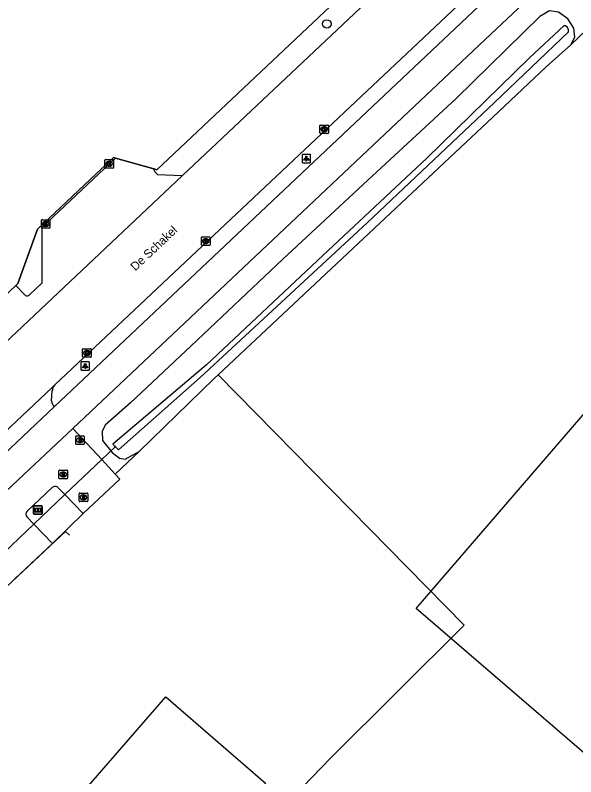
# Model space of a CAD drawing. Extents: x 156141 to 158132, y 385651 to 388399.
# Drawn here: x 156374.9 to 156440.2, y 387384.8 to 387473.5 of the extents above; entities that cross this region are included whole.
import ezdxf

# ---------------------------------------------------------------- set-up
doc = ezdxf.new("R2010")
doc.units = 0
for name, color, linetype in [('IMGEO_Berm_groen', 7, 'Continuous'), ('IMGEO_Boom', 7, 'Continuous'), ('IMGEO_Brandkraan', 7, 'Continuous'), ('IMGEO_Duiker', 7, 'Continuous'), ('IMGEO_Erf', 7, 'Continuous'), ('IMGEO_Fietspad_gesloten', 7, 'Continuous'), ('IMGEO_Grasland_agrarisch', 7, 'Continuous'), ('IMGEO_Groenvoorziening', 7, 'Continuous'), ('IMGEO_Hek', 7, 'Continuous'), ('IMGEO_Informatiebord', 7, 'Continuous'), ('IMGEO_Kolk', 7, 'Continuous'), ('IMGEO_Lichtpunt', 7, 'Continuous'), ('IMGEO_Openbare_ruimte_label', 7, 'Continuous'), ('IMGEO_Pand', 7, 'Continuous'), ('IMGEO_Pand_vergunning_verleend', 7, 'Continuous'), ('IMGEO_Rijbaan_lokaal_gesloten', 7, 'Continuous'), ('IMGEO_Rijbaan_lokaal_open', 7, 'Continuous'), ('IMGEO_Rioolput', 7, 'Continuous'), ('IMGEO_Waterloop', 7, 'Continuous')]:
    doc.layers.add(name, color=color, linetype=linetype)

msp = doc.modelspace()

# ---------------------------------------------------------------- linework, layer by layer
at = {"layer": 'IMGEO_Berm_groen'}
for points in [[(156391.052, 387455.634), (156391.387, 387455.539), (156425.089, 387487.348), (156452.106, 387512.72), (156457.451, 387517.769)], [(156439.579, 387470.075), (156445.188, 387475.47)], [(156439.579, 387470.075), (156440.055, 387470.978), (156439.936, 387472.035), (156439.259, 387473.121), (156438.152, 387473.891), (156437.128, 387474.069), (156435.984, 387473.375), (156426.238, 387463.827), (156415.973, 387454.322), (156406.042, 387445.13), (156395.379, 387435.028), (156388.319, 387428.383), (156385.37, 387425.775), (156385.007, 387425.036), (156385.052, 387424.008), (156386.187, 387422.587), (156387.045, 387421.935), (156387.718, 387421.807), (156389.316, 387422.698)], [(156386.547, 387420.081), (156389.316, 387422.698)], [(156382.82, 387415.469), (156379.24, 387412.002)]]:
    msp.add_lwpolyline(points, dxfattribs=at)
at = {"layer": 'IMGEO_Boom'}
msp.add_circle((156411.182, 387472.533), 0.489, dxfattribs=at)
at = {"layer": 'IMGEO_Brandkraan'}
for p, q in [((156381.941, 387423.601), (156381.941, 387424.453)), ((156382.016, 387424.527), (156382.868, 387424.527)), ((156382.429, 387424.307), (156382.454, 387424.307)), ((156382.942, 387424.453), (156382.942, 387423.601)), ((156382.868, 387423.527), (156382.016, 387423.527)), ((156382.452, 387423.747), (156382.427, 387423.747))]:
    msp.add_line(p, q, dxfattribs=at)
for points in [[(156381.941, 387423.601), (156381.941, 387424.453)], [(156382.016, 387424.527), (156382.868, 387424.527)], [(156382.289, 387424.227), (156382.289, 387423.827), (156382.502, 387423.827)], [(156382.52, 387424.227), (156382.289, 387424.227)], [(156382.942, 387424.453), (156382.942, 387423.601)], [(156382.868, 387423.527), (156382.016, 387423.527)], [(156382.468, 387424.146), (156382.414, 387424.146), (156382.414, 387424.07)], [(156382.414, 387424.07), (156382.467, 387424.07)], [(156382.476, 387423.994), (156382.414, 387423.994), (156382.414, 387423.913)], [(156382.414, 387423.913), (156382.476, 387423.913)]]:
    msp.add_lwpolyline(points, dxfattribs=at)
for centre, radius, start, end in [((156382.018, 387424.451), 0.0765, 91.55205, 178.44795), ((156382.018, 387424.451), 0.0765, 91.55205, 178.44795), ((156382.524, 387424.082), 0.145, 59.4692, 91.53667), ((156382.866, 387424.451), 0.0765, 1.55205, 88.44795), ((156382.866, 387424.451), 0.0765, 1.55205, 88.44795), ((156382.018, 387423.603), 0.0765, 181.55205, 268.44795), ((156382.018, 387423.603), 0.0765, 181.55205, 268.44795), ((156382.469, 387424.108), 0.0379, 267.82845, 90.93552), ((156382.477, 387423.953), 0.0404, 269.87594, 90.50774), ((156382.508, 387424.078), 0.251, 268.66757, 293.53466), ((156382.549, 387424.129), 0.0922, 285.51372, 58.15012), ((156382.554, 387423.937), 0.105, 301.31148, 78.98903), ((156382.866, 387423.603), 0.0765, 271.55205, 358.44795), ((156382.866, 387423.603), 0.0765, 271.55205, 358.44795)]:
    msp.add_arc(centre, radius, start, end, dxfattribs=at)
for centre, major_axis, ratio, start_param, end_param in [((156382.428, 387424.027), (-0.387, 0.002), 0.722429, 4.712389, 7.853982), ((156382.453, 387424.027), (-0.39, 0.002), 0.717154, 1.570796, 4.712389)]:
    msp.add_ellipse(centre, major_axis=major_axis, ratio=ratio, start_param=start_param, end_param=end_param, dxfattribs=at)
at = {"layer": 'IMGEO_Duiker'}
msp.add_lwpolyline([(156370.963, 387408.483), (156372.047, 387409.51), (156372.712, 387410.141), (156377.057, 387414.261), (156380.682, 387417.698), (156384.979, 387421.773), (156385.729, 387422.483), (156386.614, 387423.323)], dxfattribs=at)
at = {"layer": 'IMGEO_Erf'}
msp.add_lwpolyline([(156389.316, 387422.698), (156398.063, 387431.195), (156398.534, 387431.637)], dxfattribs=at)
at = {"layer": 'IMGEO_Fietspad_gesloten'}
for points in [[(156585.415, 387620.086), (156578.126, 387613.433), (156551.398, 387590.304), (156495.527, 387537.568), (156379.452, 387427.902)], [(156590.669, 387620.135), (156581.442, 387611.597), (156554.376, 387588.321), (156498.217, 387535.194), (156430.268, 387471.316), (156381.614, 387425.402)]]:
    msp.add_lwpolyline(points, dxfattribs=at)
at = {"layer": 'IMGEO_Grasland_agrarisch'}
for points in [[(156398.534, 387431.637), (156430.521, 387461.648), (156436.708, 387467.537), (156439.579, 387470.075)], [(156406.207, 387381.373), (156411.668, 387387.025), (156427.155, 387402.46), (156398.534, 387431.637)]]:
    msp.add_lwpolyline(points, dxfattribs=at)
at = {"layer": 'IMGEO_Groenvoorziening'}
msp.add_lwpolyline([(156374.956, 387442.047), (156375.204, 387442.28), (156377.511, 387448.6), (156386.35, 387456.964), (156386.592, 387456.896)], dxfattribs=at)
at = {"layer": 'IMGEO_Hek'}
for points in [[(156548.867, 387605.742), (156540.59, 387597.212), (156536.23, 387592.718), (156529.863, 387586.065), (156510.629, 387567.966), (156497.455, 387555.488), (156496.881, 387556.093), (156495.089, 387554.361), (156495.654, 387553.795), (156471.142, 387530.701), (156467.766, 387527.512), (156457.451, 387517.769), (156452.106, 387512.72), (156425.089, 387487.348), (156391.387, 387455.539), (156391.052, 387455.634), (156386.592, 387456.896), (156386.35, 387456.964), (156377.511, 387448.6), (156375.204, 387442.28), (156374.956, 387442.047), (156370.988, 387438.316), (156367.952, 387435.462), (156364.053, 387431.796)], [(156343.435, 387366.714), (156343.833, 387368.977), (156344.263, 387371.266), (156344.924, 387373.465), (156345.713, 387375.673), (156346.624, 387377.803), (156347.657, 387379.878), (156348.858, 387381.869), (156350.164, 387383.782), (156351.592, 387385.597), (156353.137, 387387.325), (156354.792, 387388.966), (156373.938, 387406.992), (156380.213, 387412.891), (156380.728, 387413.365)], [(156381.228, 387412.955), (156380.732, 387413.408)]]:
    msp.add_lwpolyline(points, dxfattribs=at)
at = {"layer": 'IMGEO_Informatiebord'}
for p, q in [((156377.039, 387415.491), (156377.039, 387416.291)), ((156377.039, 387416.291), (156377.039, 387415.491)), ((156377.139, 387416.391), (156377.929, 387416.391)), ((156377.929, 387416.391), (156377.139, 387416.391)), ((156378.029, 387416.291), (156378.029, 387415.491)), ((156378.029, 387415.491), (156378.029, 387416.291)), ((156377.929, 387415.391), (156377.139, 387415.391)), ((156377.139, 387415.391), (156377.929, 387415.391))]:
    msp.add_line(p, q, dxfattribs=at)
for points in [[(156377.14, 387416.123), (156377.928, 387416.123), (156377.928, 387415.659), (156377.14, 387415.659), (156377.14, 387416.123)], [(156377.205, 387416.058), (156377.205, 387415.724), (156377.48, 387415.724), (156377.481, 387415.937), (156377.585, 387415.938), (156377.586, 387415.724), (156377.863, 387415.724), (156377.863, 387416.058), (156377.587, 387416.058), (156377.587, 387415.978), (156377.481, 387415.978), (156377.481, 387416.058), (156377.205, 387416.058)]]:
    msp.add_lwpolyline(points, dxfattribs=at)
for centre, start, end in [((156377.139, 387416.291), 90, 180), ((156377.139, 387416.291), 90, 180), ((156377.929, 387416.291), 0, 90), ((156377.929, 387416.291), 360, 90), ((156377.139, 387415.491), 180, 270), ((156377.139, 387415.491), 180, 270), ((156377.929, 387415.491), 270, 0), ((156377.929, 387415.491), 270, 0)]:
    msp.add_arc(centre, 0.1, start, end, dxfattribs=at)
at = {"layer": 'IMGEO_Kolk'}
for p, q in [((156410.371, 387459.823), (156410.371, 387460.675)), ((156410.446, 387460.749), (156411.298, 387460.749)), ((156411.372, 387460.675), (156411.372, 387459.823)), ((156411.298, 387459.749), (156410.446, 387459.749)), ((156410.882, 387459.969), (156410.857, 387459.969)), ((156410.859, 387460.529), (156410.884, 387460.529)), ((156385.33, 387455.789), (156385.33, 387456.641)), ((156385.405, 387456.715), (156386.257, 387456.715)), ((156385.818, 387456.495), (156385.843, 387456.495)), ((156386.331, 387456.641), (156386.331, 387455.789)), ((156386.257, 387455.715), (156385.405, 387455.715)), ((156385.841, 387455.935), (156385.816, 387455.935)), ((156377.946, 387448.794), (156377.946, 387449.646)), ((156378.021, 387449.72), (156378.873, 387449.72)), ((156378.434, 387449.5), (156378.459, 387449.5)), ((156378.947, 387449.646), (156378.947, 387448.794)), ((156378.873, 387448.72), (156378.021, 387448.72)), ((156378.457, 387448.94), (156378.432, 387448.94)), ((156396.581, 387446.796), (156396.581, 387447.648)), ((156396.656, 387447.722), (156397.508, 387447.722)), ((156397.069, 387447.502), (156397.094, 387447.502)), ((156397.582, 387447.648), (156397.582, 387446.796)), ((156397.508, 387446.722), (156396.656, 387446.722)), ((156397.092, 387446.942), (156397.067, 387446.942)), ((156382.748, 387433.761), (156382.748, 387434.613)), ((156382.823, 387434.687), (156383.675, 387434.687)), ((156383.236, 387434.467), (156383.261, 387434.467)), ((156383.749, 387434.613), (156383.749, 387433.761)), ((156383.675, 387433.687), (156382.823, 387433.687)), ((156383.259, 387433.907), (156383.234, 387433.907))]:
    msp.add_line(p, q, dxfattribs=at)
for points in [[(156410.371, 387459.823), (156410.371, 387460.675)], [(156410.446, 387460.749), (156411.298, 387460.749)], [(156411.372, 387460.675), (156411.372, 387459.823)], [(156411.298, 387459.749), (156410.446, 387459.749)], [(156410.692, 387460.449), (156410.815, 387460.449), (156410.815, 387460.298), (156410.945, 387460.449), (156411.109, 387460.449), (156410.963, 387460.298), (156411.116, 387460.049), (156410.964, 387460.049), (156410.879, 387460.213), (156410.815, 387460.146), (156410.815, 387460.049), (156410.692, 387460.049), (156410.692, 387460.449)], [(156385.33, 387455.789), (156385.33, 387456.641)], [(156385.405, 387456.715), (156386.257, 387456.715)], [(156385.651, 387456.415), (156385.774, 387456.415), (156385.774, 387456.264), (156385.904, 387456.415), (156386.068, 387456.415), (156385.922, 387456.264), (156386.075, 387456.015), (156385.923, 387456.015), (156385.838, 387456.179), (156385.774, 387456.112), (156385.774, 387456.015), (156385.651, 387456.015), (156385.651, 387456.415)], [(156386.331, 387456.641), (156386.331, 387455.789)], [(156386.257, 387455.715), (156385.405, 387455.715)], [(156377.946, 387448.794), (156377.946, 387449.646)], [(156378.021, 387449.72), (156378.873, 387449.72)], [(156378.267, 387449.42), (156378.39, 387449.42), (156378.39, 387449.269), (156378.52, 387449.42), (156378.684, 387449.42), (156378.538, 387449.269), (156378.691, 387449.02), (156378.539, 387449.02), (156378.454, 387449.184), (156378.39, 387449.117), (156378.39, 387449.02), (156378.267, 387449.02), (156378.267, 387449.42)], [(156378.947, 387449.646), (156378.947, 387448.794)], [(156378.873, 387448.72), (156378.021, 387448.72)], [(156396.581, 387446.796), (156396.581, 387447.648)], [(156396.656, 387447.722), (156397.508, 387447.722)], [(156396.902, 387447.422), (156397.025, 387447.422), (156397.025, 387447.271), (156397.155, 387447.422), (156397.319, 387447.422), (156397.173, 387447.271), (156397.326, 387447.022), (156397.174, 387447.022), (156397.089, 387447.186), (156397.025, 387447.119), (156397.025, 387447.022), (156396.902, 387447.022), (156396.902, 387447.422)], [(156397.582, 387447.648), (156397.582, 387446.796)], [(156397.508, 387446.722), (156396.656, 387446.722)], [(156382.748, 387433.761), (156382.748, 387434.613)], [(156382.823, 387434.687), (156383.675, 387434.687)], [(156383.069, 387434.387), (156383.192, 387434.387), (156383.192, 387434.236), (156383.322, 387434.387), (156383.486, 387434.387), (156383.34, 387434.236), (156383.493, 387433.987), (156383.341, 387433.987), (156383.256, 387434.151), (156383.192, 387434.084), (156383.192, 387433.987), (156383.069, 387433.987), (156383.069, 387434.387)], [(156383.749, 387434.613), (156383.749, 387433.761)], [(156383.675, 387433.687), (156382.823, 387433.687)]]:
    msp.add_lwpolyline(points, dxfattribs=at)
for centre, start, end in [((156410.448, 387460.673), 91.55205, 178.44795), ((156410.448, 387460.673), 91.55205, 178.44795), ((156411.296, 387460.673), 1.55205, 88.44795), ((156411.296, 387460.673), 1.55205, 88.44795), ((156410.448, 387459.825), 181.55205, 268.44795), ((156410.448, 387459.825), 181.55205, 268.44795), ((156411.296, 387459.825), 271.55205, 358.44795), ((156411.296, 387459.825), 271.55205, 358.44795), ((156385.407, 387456.639), 91.55205, 178.44795), ((156385.407, 387456.639), 91.55205, 178.44795), ((156386.255, 387456.639), 1.55205, 88.44795), ((156386.255, 387456.639), 1.55205, 88.44795), ((156385.407, 387455.791), 181.55205, 268.44795), ((156385.407, 387455.791), 181.55205, 268.44795), ((156386.255, 387455.791), 271.55205, 358.44795), ((156386.255, 387455.791), 271.55205, 358.44795), ((156378.023, 387449.644), 91.55205, 178.44795), ((156378.023, 387449.644), 91.55205, 178.44795), ((156378.871, 387449.644), 1.55205, 88.44795), ((156378.871, 387449.644), 1.55205, 88.44795), ((156378.023, 387448.796), 181.55205, 268.44795), ((156378.023, 387448.796), 181.55205, 268.44795), ((156378.871, 387448.796), 271.55205, 358.44795), ((156378.871, 387448.796), 271.55205, 358.44795), ((156396.658, 387447.646), 91.55205, 178.44795), ((156396.658, 387447.646), 91.55205, 178.44795), ((156397.506, 387447.646), 1.55205, 88.44795), ((156397.506, 387447.646), 1.55205, 88.44795), ((156396.658, 387446.798), 181.55205, 268.44795), ((156396.658, 387446.798), 181.55205, 268.44795), ((156397.506, 387446.798), 271.55205, 358.44795), ((156397.506, 387446.798), 271.55205, 358.44795), ((156382.825, 387434.611), 91.55205, 178.44795), ((156382.825, 387434.611), 91.55205, 178.44795), ((156383.673, 387434.611), 1.55205, 88.44795), ((156383.673, 387434.611), 1.55205, 88.44795), ((156382.825, 387433.763), 181.55205, 268.44795), ((156382.825, 387433.763), 181.55205, 268.44795), ((156383.673, 387433.763), 271.55205, 358.44795), ((156383.673, 387433.763), 271.55205, 358.44795)]:
    msp.add_arc(centre, 0.0765, start, end, dxfattribs=at)
for centre, major_axis, ratio, start_param, end_param in [((156410.858, 387460.249), (-0.387, 0.002), 0.722429, 4.712389, 7.853982), ((156410.883, 387460.249), (-0.39, 0.002), 0.717154, 1.570796, 4.712389), ((156385.817, 387456.215), (-0.387, 0.002), 0.722429, 4.712389, 7.853982), ((156385.842, 387456.215), (-0.39, 0.002), 0.717154, 1.570796, 4.712389), ((156378.433, 387449.22), (-0.387, 0.002), 0.722429, 4.712389, 7.853982), ((156378.458, 387449.22), (-0.39, 0.002), 0.717154, 1.570796, 4.712389), ((156397.068, 387447.222), (-0.387, 0.002), 0.722429, 4.712389, 7.853982), ((156397.093, 387447.222), (-0.39, 0.002), 0.717154, 1.570796, 4.712389), ((156383.235, 387434.187), (-0.387, 0.002), 0.722429, 4.712389, 7.853982), ((156383.26, 387434.187), (-0.39, 0.002), 0.717154, 1.570796, 4.712389)]:
    msp.add_ellipse(centre, major_axis=major_axis, ratio=ratio, start_param=start_param, end_param=end_param, dxfattribs=at)
at = {"layer": 'IMGEO_Lichtpunt'}
for p, q in [((156408.305, 387457.237), (156408.305, 387456.43)), ((156408.305, 387457.237), (156408.305, 387456.43)), ((156409.207, 387457.332), (156408.399, 387457.332)), ((156409.207, 387457.332), (156408.399, 387457.332)), ((156409.301, 387456.43), (156409.301, 387457.237)), ((156409.301, 387456.43), (156409.301, 387457.237)), ((156408.399, 387456.336), (156409.207, 387456.336)), ((156408.399, 387456.336), (156409.207, 387456.336)), ((156383.458, 387433.167), (156382.65, 387433.167)), ((156383.458, 387433.167), (156382.65, 387433.167)), ((156382.556, 387433.072), (156382.556, 387432.265)), ((156382.556, 387433.072), (156382.556, 387432.265)), ((156383.552, 387432.265), (156383.552, 387433.072)), ((156383.552, 387432.265), (156383.552, 387433.072)), ((156382.65, 387432.171), (156383.458, 387432.171)), ((156382.65, 387432.171), (156383.458, 387432.171))]:
    msp.add_line(p, q, dxfattribs=at)
for points in [[(156408.679, 387456.901), (156408.718, 387456.873), (156408.53, 387456.611), (156408.492, 387456.638), (156408.679, 387456.901)], [(156408.781, 387456.853), (156408.828, 387456.853), (156408.828, 387456.531), (156408.781, 387456.531), (156408.781, 387456.853)], [(156408.891, 387456.873), (156408.929, 387456.9), (156409.116, 387456.638), (156409.077, 387456.61), (156408.891, 387456.873)], [(156382.93, 387432.736), (156382.969, 387432.708), (156382.781, 387432.446), (156382.743, 387432.473), (156382.93, 387432.736)], [(156383.032, 387432.688), (156383.079, 387432.688), (156383.079, 387432.366), (156383.032, 387432.366), (156383.032, 387432.688)], [(156383.142, 387432.708), (156383.18, 387432.735), (156383.367, 387432.473), (156383.328, 387432.445), (156383.142, 387432.708)]]:
    msp.add_lwpolyline(points, dxfattribs=at)
for centre in [(156408.804, 387457.035), (156383.055, 387432.87)]:
    msp.add_circle(centre, 0.0994, dxfattribs=at)
for centre, start, end in [((156408.399, 387457.237), 90, 180), ((156408.399, 387457.237), 90, 180), ((156409.207, 387457.237), 0, 90), ((156409.207, 387457.237), 0, 90), ((156408.399, 387456.43), 180, 270), ((156408.399, 387456.43), 180, 270), ((156409.207, 387456.43), 270, 0), ((156409.207, 387456.43), 270, 360), ((156382.65, 387433.072), 90, 180), ((156382.65, 387433.072), 90, 180), ((156383.458, 387433.072), 0, 90), ((156383.458, 387433.072), 0, 90), ((156382.65, 387432.265), 180, 270), ((156382.65, 387432.265), 180, 270), ((156383.458, 387432.265), 270, 0), ((156383.458, 387432.265), 270, 360)]:
    msp.add_arc(centre, 0.0946, start, end, dxfattribs=at)
at = {"layer": 'IMGEO_Pand'}
msp.add_lwpolyline([(156439.864, 387285.556), (156403.261, 387317.306), (156402.856, 387316.839), (156358.716, 387355.235), (156378.098, 387377.576), (156378.551, 387377.182), (156378.768, 387377.431), (156377.091, 387378.886), (156380.197, 387382.512), (156381.87, 387381.054), (156382.876, 387382.207), (156382.423, 387382.601), (156392.451, 387394.11), (156404.049, 387384.075), (156403.635, 387383.598), (156404.58, 387382.781), (156406.207, 387381.373)], dxfattribs=at)
at = {"layer": 'IMGEO_Pand_vergunning_verleend'}
msp.add_lwpolyline([(156421.574, 387404.419), (156466.483, 387456.553), (156544.064, 387389.723), (156499.154, 387337.589), (156421.574, 387404.419)], dxfattribs=at)
at = {"layer": 'IMGEO_Rijbaan_lokaal_gesloten'}
for points in [[(156379.528, 387430.462), (156494.497, 387538.848), (156552.666, 387593.555), (156552.503, 387593.766), (156576.876, 387614.53)], [(156394.388, 387454.876), (156461.719, 387518.363)], [(156370.883, 387432.712), (156394.388, 387454.876)], [(156364.585, 387416.367), (156379.199, 387430.181), (156379.528, 387430.462)]]:
    msp.add_lwpolyline(points, dxfattribs=at)
at = {"layer": 'IMGEO_Rijbaan_lokaal_open'}
for points in [[(156376.612, 387440.982), (156378.05, 387442.373), (156378.049, 387448.843), (156386.592, 387456.896)], [(156386.592, 387456.896), (156391.052, 387455.634)], [(156391.172, 387455.29), (156391.47, 387454.987), (156394.388, 387454.876)], [(156370.988, 387438.316), (156374.956, 387442.047)], [(156374.956, 387442.047), (156375.974, 387440.996)], [(156379.144, 387428.622), (156379.192, 387429.766)], [(156379.452, 387427.902), (156367.052, 387416.223)], [(156381.614, 387425.402), (156374.588, 387418.771), (156369.296, 387413.778)], [(156386.547, 387420.081), (156384.979, 387421.773), (156381.614, 387425.402)], [(156382.82, 387415.469), (156387.098, 387419.487), (156386.547, 387420.081)], [(156376.291, 387415.76), (156379.214, 387418.495)], [(156379.919, 387418.493), (156380.682, 387417.698), (156382.82, 387415.469)], [(156379.24, 387412.002), (156377.057, 387414.261), (156376.299, 387415.045)], [(156374.85, 387407.865), (156379.24, 387412.002)]]:
    msp.add_lwpolyline(points, dxfattribs=at)
for centre, radius, start, end in [((156391.417, 387455.568), 0.371, 169.82859, 228.63275), ((156376.299, 387441.276), 0.429, 220.69604, 316.78981), ((156380.2, 387429.709), 1.009, 131.72182, 176.73952), ((156380.306, 387428.693), 1.164, 183.4976, 222.82273), ((156379.566, 387418.148), 0.494, 44.33418, 135.34074), ((156376.666, 387415.407), 0.515, 136.68088, 224.60121)]:
    msp.add_arc(centre, radius, start, end, dxfattribs=at)
at = {"layer": 'IMGEO_Rioolput'}
for p, q in [((156379.992, 387419.611), (156379.992, 387420.463)), ((156380.067, 387420.537), (156380.919, 387420.537)), ((156380.48, 387420.317), (156380.505, 387420.317)), ((156380.993, 387420.463), (156380.993, 387419.611)), ((156380.919, 387419.537), (156380.067, 387419.537)), ((156380.503, 387419.757), (156380.478, 387419.757)), ((156382.34, 387416.943), (156382.34, 387417.795)), ((156382.415, 387417.869), (156383.267, 387417.869)), ((156382.828, 387417.649), (156382.853, 387417.649)), ((156383.341, 387417.795), (156383.341, 387416.943)), ((156383.267, 387416.869), (156382.415, 387416.869)), ((156382.851, 387417.089), (156382.826, 387417.089))]:
    msp.add_line(p, q, dxfattribs=at)
for points in [[(156379.992, 387419.611), (156379.992, 387420.463)], [(156380.067, 387420.537), (156380.919, 387420.537)], [(156380.581, 387420.235), (156380.329, 387420.237), (156380.329, 387419.837)], [(156380.329, 387419.837), (156380.453, 387419.837), (156380.453, 387419.999), (156380.464, 387419.999)], [(156380.507, 387420.156), (156380.453, 387420.156), (156380.453, 387420.075)], [(156380.453, 387420.075), (156380.505, 387420.075)], [(156380.511, 387419.97), (156380.582, 387419.837), (156380.722, 387419.837), (156380.657, 387419.963)], [(156380.993, 387420.463), (156380.993, 387419.611)], [(156380.919, 387419.537), (156380.067, 387419.537)], [(156382.34, 387416.943), (156382.34, 387417.795)], [(156382.415, 387417.869), (156383.267, 387417.869)], [(156382.929, 387417.567), (156382.677, 387417.569), (156382.677, 387417.169)], [(156382.677, 387417.169), (156382.801, 387417.169), (156382.801, 387417.331), (156382.812, 387417.331)], [(156382.855, 387417.488), (156382.801, 387417.488), (156382.801, 387417.407)], [(156382.801, 387417.407), (156382.853, 387417.407)], [(156382.859, 387417.302), (156382.93, 387417.169), (156383.07, 387417.169), (156383.005, 387417.295)], [(156383.341, 387417.795), (156383.341, 387416.943)], [(156383.267, 387416.869), (156382.415, 387416.869)]]:
    msp.add_lwpolyline(points, dxfattribs=at)
for centre, radius, start, end in [((156380.069, 387420.461), 0.0765, 91.55205, 178.44795), ((156380.069, 387420.461), 0.0765, 91.55205, 178.44795), ((156380.463, 387419.946), 0.0533, 26.02933, 88.69889), ((156380.489, 387420.264), 0.19, 274.7715, 282.96867), ((156380.513, 387420.06), 0.0964, 77.00612, 93.18647), ((156380.527, 387420.117), 0.0378, 276.66336, 79.67722), ((156380.58, 387420.125), 0.109, 350.36119, 89.41601), ((156380.578, 387420.125), 0.112, 277.58423, 350.98172), ((156380.562, 387419.91), 0.108, 29.51342, 73.79051), ((156380.917, 387420.461), 0.0765, 1.55205, 88.44795), ((156380.917, 387420.461), 0.0765, 1.55205, 88.44795), ((156380.069, 387419.613), 0.0765, 181.55205, 268.44795), ((156380.069, 387419.613), 0.0765, 181.55205, 268.44795), ((156380.917, 387419.613), 0.0765, 271.55205, 358.44795), ((156380.917, 387419.613), 0.0765, 271.55205, 358.44795), ((156382.417, 387417.793), 0.0765, 91.55205, 178.44795), ((156382.417, 387417.793), 0.0765, 91.55205, 178.44795), ((156382.811, 387417.278), 0.0533, 26.02933, 88.69889), ((156382.837, 387417.596), 0.19, 274.7715, 282.96867), ((156382.861, 387417.392), 0.0964, 77.00612, 93.18647), ((156382.875, 387417.449), 0.0378, 276.66336, 79.67722), ((156382.928, 387417.457), 0.109, 350.36119, 89.41601), ((156382.926, 387417.457), 0.112, 277.58423, 350.98172), ((156382.91, 387417.242), 0.108, 29.51342, 73.79051), ((156383.265, 387417.793), 0.0765, 1.55205, 88.44795), ((156383.265, 387417.793), 0.0765, 1.55205, 88.44795), ((156382.417, 387416.945), 0.0765, 181.55205, 268.44795), ((156382.417, 387416.945), 0.0765, 181.55205, 268.44795), ((156383.265, 387416.945), 0.0765, 271.55205, 358.44795), ((156383.265, 387416.945), 0.0765, 271.55205, 358.44795)]:
    msp.add_arc(centre, radius, start, end, dxfattribs=at)
for centre, major_axis, ratio, start_param, end_param in [((156380.479, 387420.037), (-0.387, 0.002), 0.722429, 4.712389, 7.853982), ((156380.504, 387420.037), (-0.39, 0.002), 0.717154, 1.570796, 4.712389), ((156382.827, 387417.369), (-0.387, 0.002), 0.722429, 4.712389, 7.853982), ((156382.852, 387417.369), (-0.39, 0.002), 0.717154, 1.570796, 4.712389)]:
    msp.add_ellipse(centre, major_axis=major_axis, ratio=ratio, start_param=start_param, end_param=end_param, dxfattribs=at)
at = {"layer": 'IMGEO_Waterloop'}
msp.add_lwpolyline([(156415.899, 387449.365), (156430.725, 387463.37), (156439.306, 387471.605), (156439.337, 387471.856), (156439.196, 387472.107), (156438.976, 387472.295), (156438.773, 387472.295), (156434.79, 387468.585), (156422.839, 387456.881), (156410.725, 387445.526), (156397.172, 387432.795), (156386.278, 387423.582), (156386.943, 387422.896), (156396.433, 387431.316), (156415.899, 387449.365)], dxfattribs=at)

# ---------------------------------------------------------------- texts
at = {"layer": 'IMGEO_Openbare_ruimte_label'}
msp.add_text('De Schakel', height=1, rotation=43.33796, dxfattribs=at).set_placement((156388.893, 387443.685))

doc.saveas('drawing.dxf')
